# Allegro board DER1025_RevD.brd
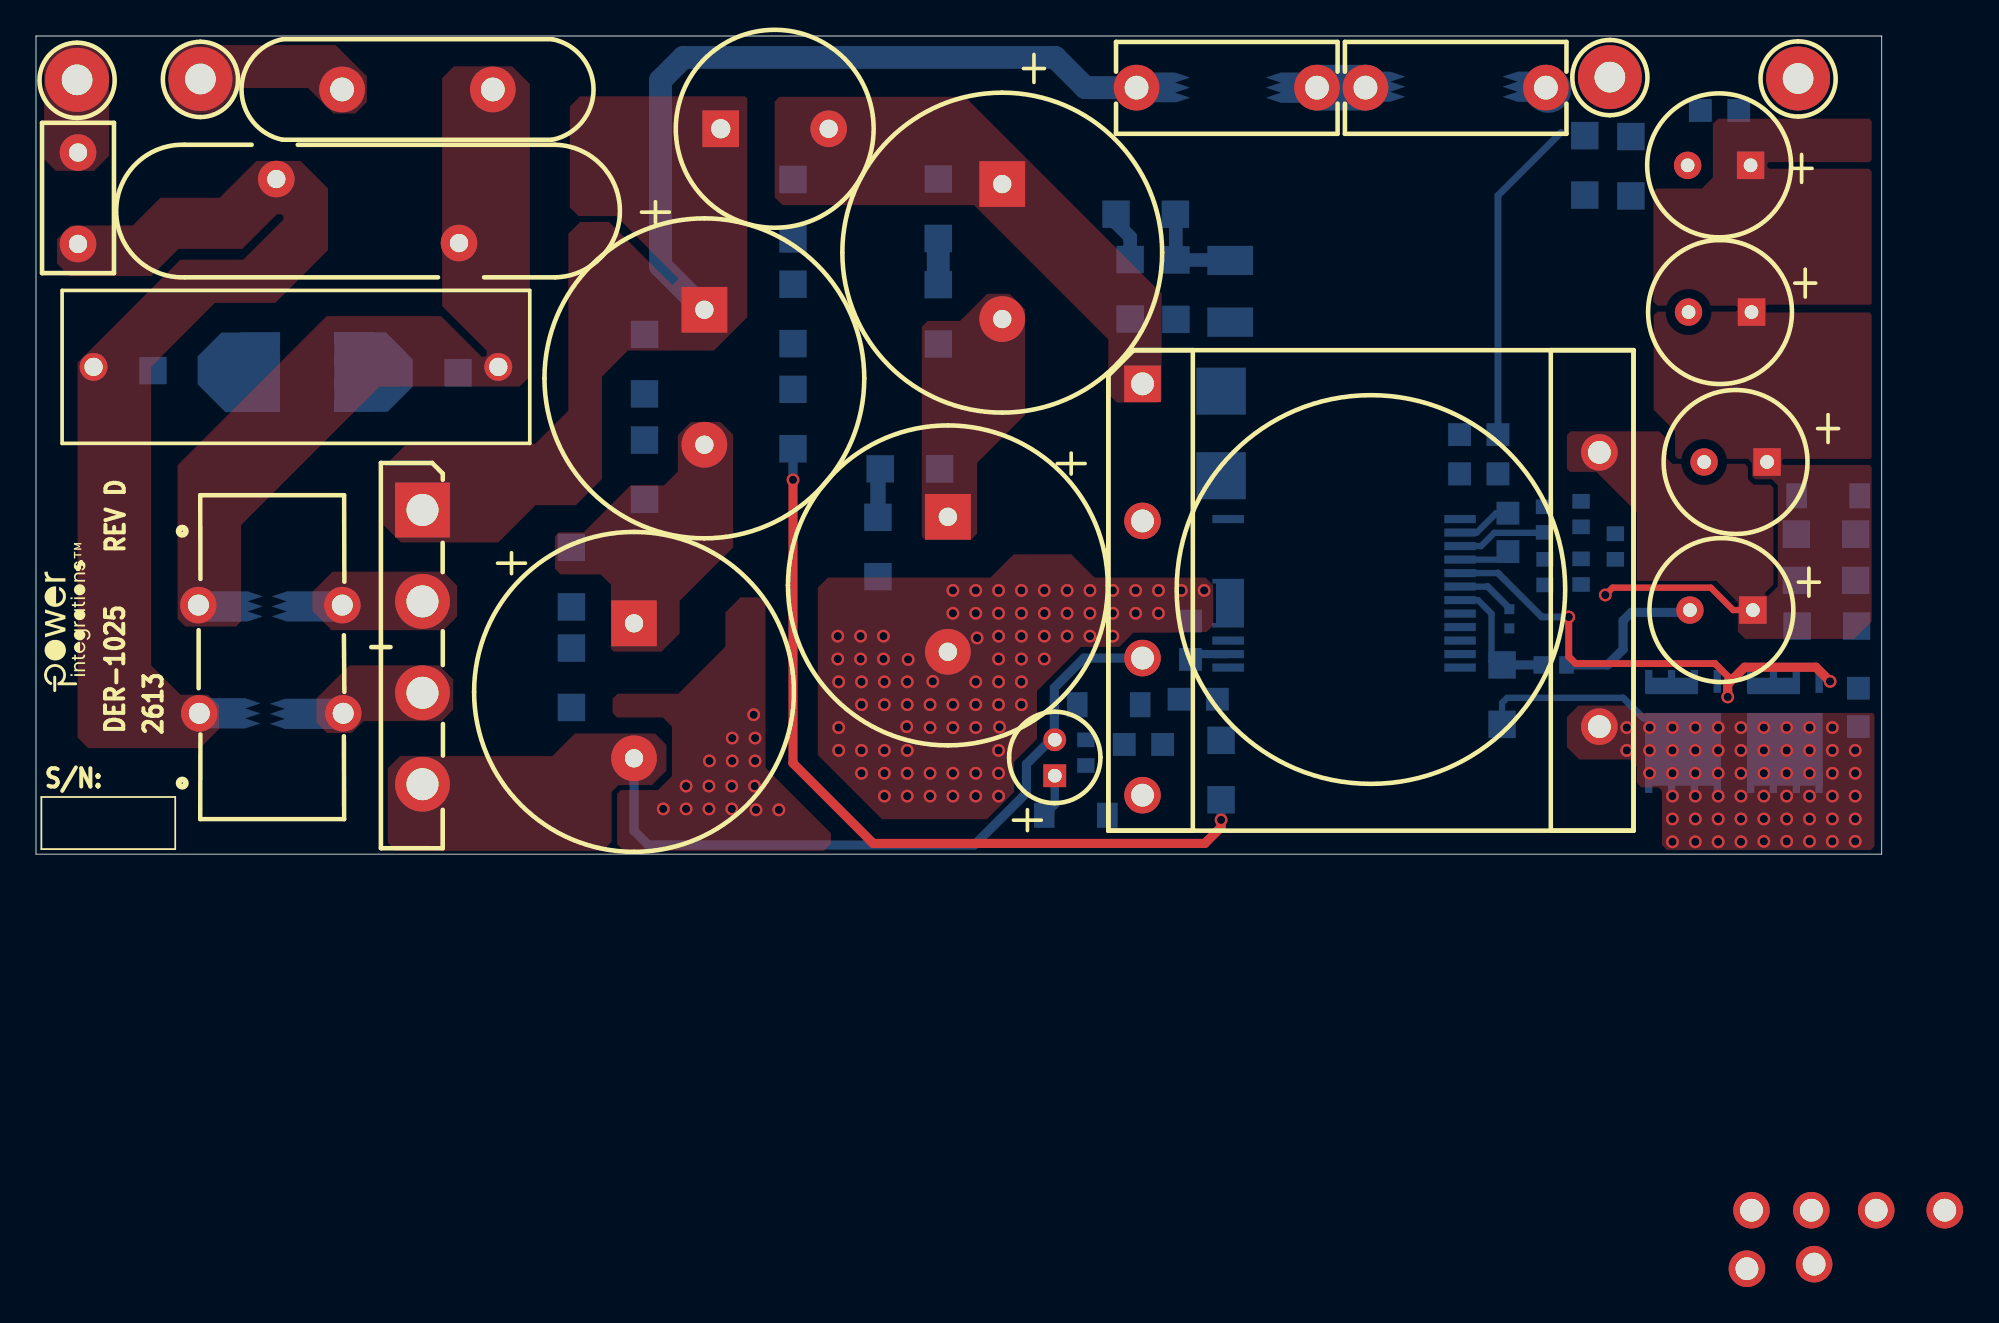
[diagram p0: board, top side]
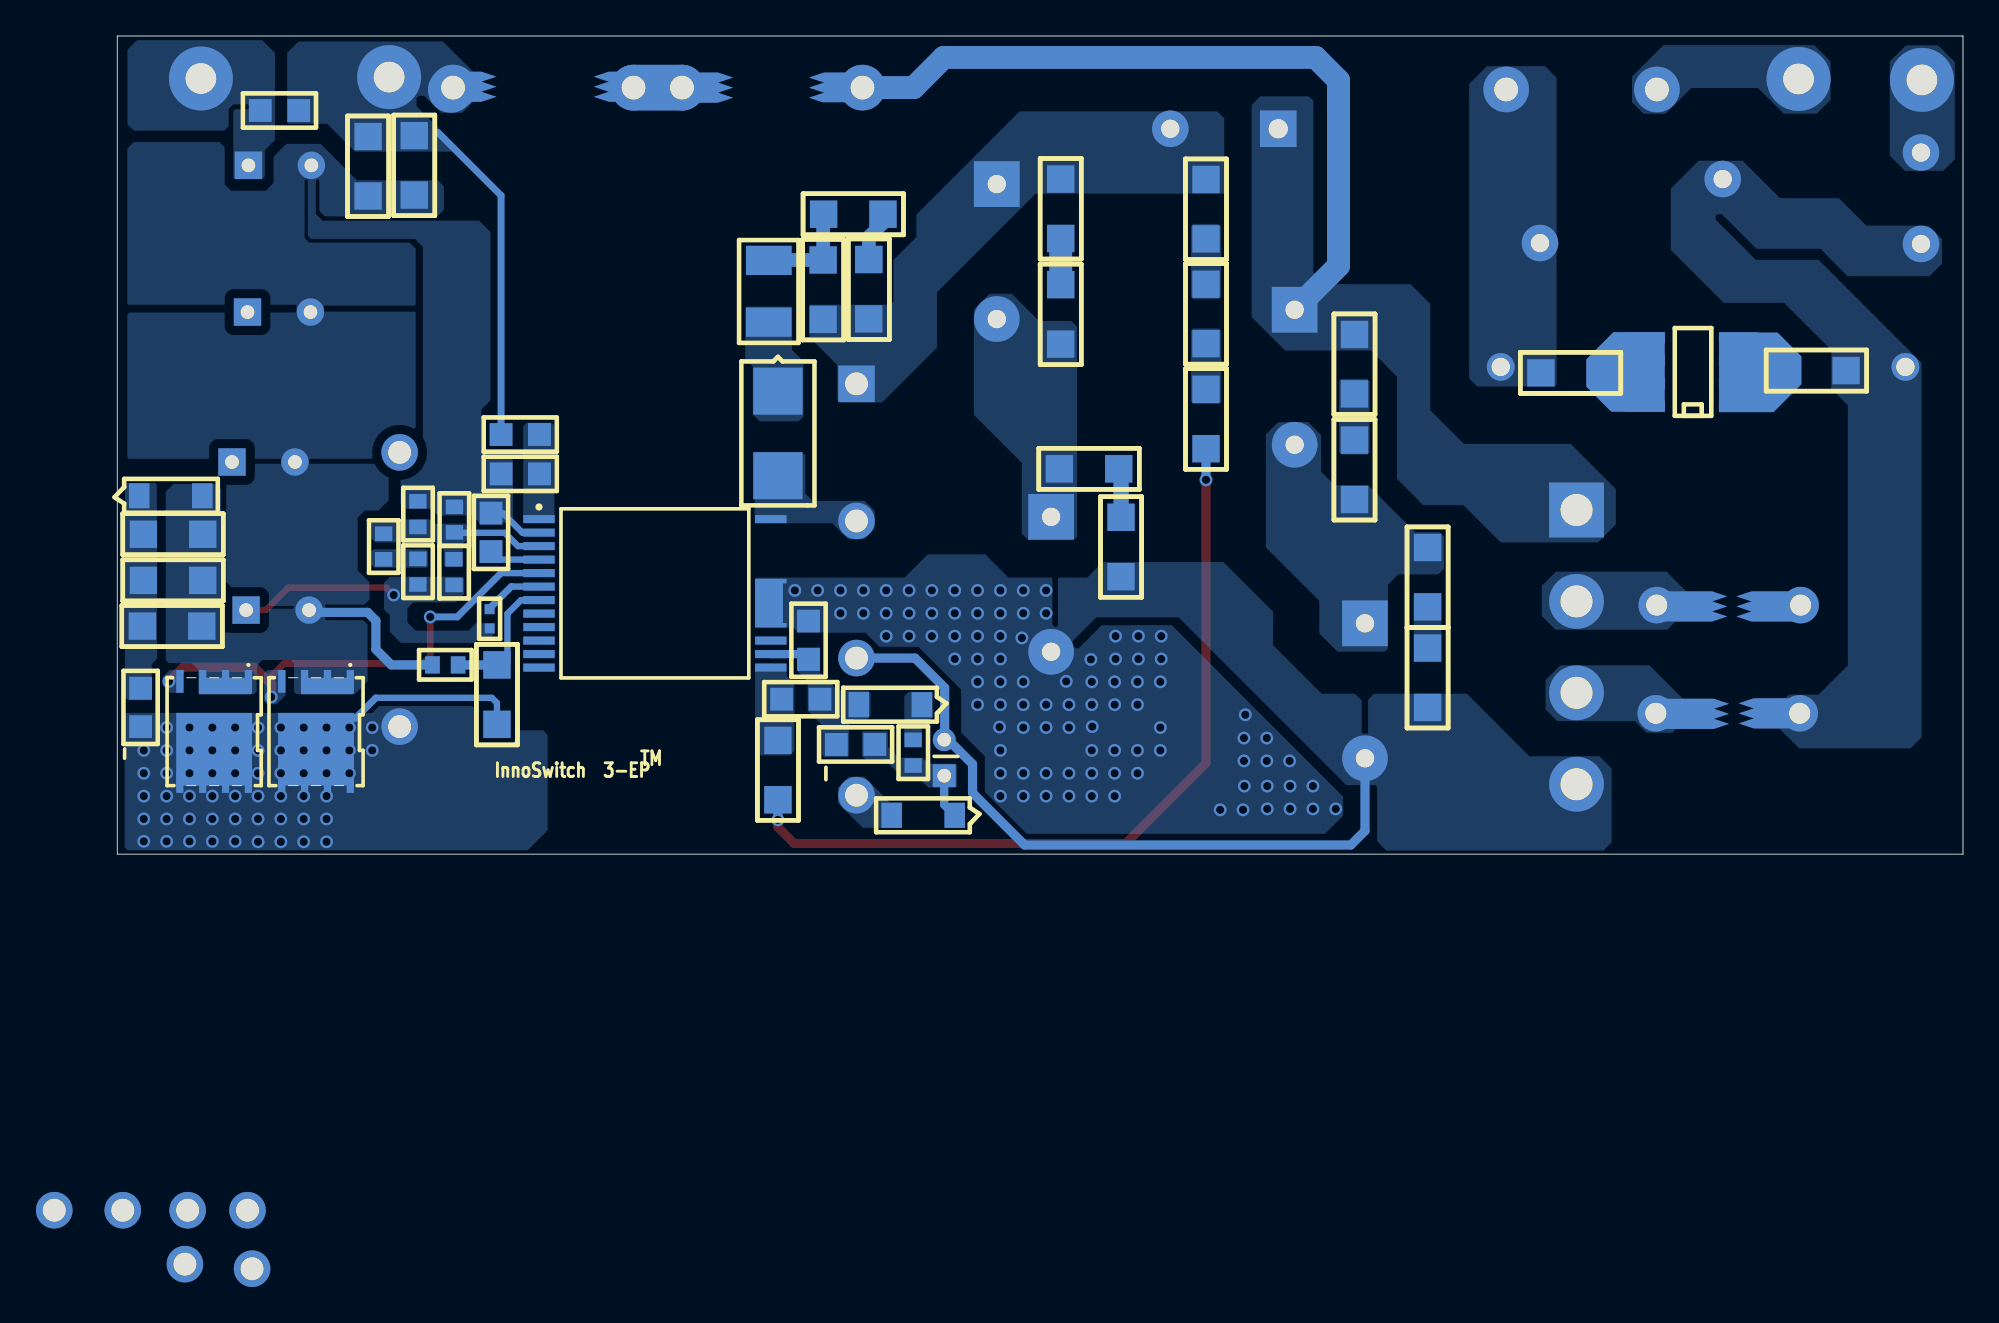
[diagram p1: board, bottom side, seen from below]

Outline 102.62 x 45.47 mm; copper layers: TOP, BOTTOM. Coordinates in mm from the lower left corner of the outline.
Outline path: 0,45.47 0,0 102.62,0 102.62,45.47 0,45.47

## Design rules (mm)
constraint set DEFAULT: min track width 0.203

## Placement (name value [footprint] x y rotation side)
BR1  GBU1010  [PIDAXBRIDGEGBU8]  21.49 19.13 270 top
C1  220 uf  [PIPOLCAPCLYD710LS300040]  37.16 30.25 270 top
C2  220 uf  [PIPOLCAPCLYD710LS300040]  33.25 12.83 270 top
C3  220 uf  [PIPOLCAPCLYD710LS300040]  53.72 37.24 270 top
C4  220 uf  [PIPOLCAPCLYD710LS300040]  50.7 18.75 270 top
C5  1 nF  [PISMC1206]  63.37 29.72 90 bottom
C6  22 uF  [PIPOLCAPCLYD5MMD030]  56.64 5.36 90 top
C7  4.7 uF  [PISMC0805]  64.19 10.82 90 bottom
C8  3.3 nF  [PISMC0805]  101.32 7.09 90 bottom
C9  2.2 uF  [PISMC0805]  81.84 18.95 270 bottom
C10  330 pF  [PISMC0603]  83.67 10.52 0 bottom
C11  4.7 uF  [PISMC0805]  81.28 21.13 180 bottom
C12  330 pF  [PISMC0603]  83.87 19.3 270 bottom
C13  10 nF  [PISMC0603]  87.81 16.38 90 bottom
C14  680 uF  [PIPOLCAPCYLD8MMD030]  95.45 13.56 180 top
C15  680 uF  [PIPOLCAPCYLD8MMD030]  96.24 21.79 180 top
C16  680 uF  [PIPOLCAPCYLD8MMD030]  95.38 30.12 180 top
C17  680 uF  [PIPOLCAPCYLD8MMD030]  95.33 38.28 180 top
C18  2.2 uF  [PISMC0805]  94.67 41.33 180 bottom
CX1  220n  [PINPCAPRAD26X8P5X18D040]  14.45 27.08 0 top
CY1  2.2 nF  [PI_NP475X200LS395D040]  61.19 42.6 0 top
CY2  2.2 nF  [PI_NP475X200LS395D040]  73.91 42.6 0 top
D1  S2T-CT  [PISMDO214AA12]  65.89 25.73 270 bottom
D2  S1MLHRVG  [PI_SM_SOD-123_12]  56.06 2.16 0 bottom
D3  UFM13PL-TP  [PI_SM_SOD-123_12]  101.4 19.91 180 bottom
F1  5 A  [PI_RST_MICROFUSE]  2.34 38.99 270 top
L  WHT  [PITPKEYSTONE125X125]  2.29 43.03 0 top
L1  9 mH  [PI4P18X8MMD046_12_43]  13.13 10.95 90 top
L4  12 uH  [PI_CHOKE_COILCRAFT_RFB1010]  41.07 40.31 0 top
N  BLK  [PITPKEYSTONE125X125]  9.14 43.08 0 top
NOREF  -  []  -317.15 -305.65 0 top
NOREF#2  -  []  0.56 8.46 90 top
NOREF#3  -  []  94.85 -242.24 0 top
NOREF#4  -  []  0 0 90 top
NOREF#5  -  []  0 45.47 0 top
Q1  AON6250  [PISMPQFN5X6B]  89.66 9.6 0 bottom
Q2  AON6250  [PISMPQFN5X6B]  95.33 9.6 0 bottom
R1  56.2 k  [PISMR1206]  6.5 26.87 0 bottom
R2  56.2 k  [PISMR1206]  20.17 26.75 0 bottom
R3  10 M  [PISMR1206]  33.83 28.88 270 bottom
R4  10 M  [PISMR1206]  33.83 23.01 270 bottom
R5  10 M  [PISMR1206]  29.77 17.04 270 bottom
R6  10 M  [PISMR1206]  29.77 11.46 270 bottom
R7  10 M  [PISMR1206]  50.16 37.52 270 bottom
R8  10 M  [PISMR1206]  50.16 31.65 270 bottom
R9  10 M  [PISMR1206]  50.24 21.41 180 bottom
R10  10 M  [PISMR1206]  46.81 18.72 270 bottom
R11  560 k  [PISMR1206]  60.83 29.74 90 bottom
R12  560 k  [PISMR1206]  60.05 35.56 0 bottom
R13  20  [PISMR1210]  66.4 32.99 270 bottom
R14  10  [PISMR0603]  58.37 4.93 90 bottom
R15  7.32 k  [PISMR0805]  60.5 6.1 0 bottom
R16  47.0  [PISMR1206]  81.51 7.21 90 bottom
R17  12  [PISMR1206]  101.17 15.21 180 bottom
R18  12  [PISMR1206]  101.22 12.67 180 bottom
R19  12  [PISMR1206]  101.17 17.78 180 bottom
R20  10  [PISMR0402]  81.92 12.55 90 bottom
R21  102 k  [PISMR0603]  83.9 14.96 90 bottom
R22  11.8 k  [PISMR0603]  85.9 18.19 90 bottom
R23  15 k  [PISMR0603]  85.9 14.99 90 bottom
R24  0.011  [PISMR1206]  86.11 36.63 90 bottom
R25  13 mOhms  [PISMR1206]  88.67 36.58 90 bottom
R32  10  [PISMR0805]  81.28 23.32 180 bottom
R33  210 k  [PISMR0805]  63.55 8.61 0 bottom
R34  2.00 M  [PISMR1206]  42.09 37.49 270 bottom
R35  2.00 M  [PISMR1206]  42.09 31.67 270 bottom
R36  2.00 M  [PISMR1206]  42.09 25.83 270 bottom
R37  1.91 M  [PISMR1206]  65.89 3.02 90 bottom
RT1  5  [PI_RAD770X220LS330D052]  25.4 42.49 180 top
RTN  BLK  [PITPKEYSTONE125X125]  87.5 43.18 0 top
RV1  820V  [PI_DISC1100X290LS400X220D040]  13.36 38.53 0 top
T1  PQ26/20  [PI_BOBBIN_BPQ26_20_12P_2]  74.22 14.71 0 top
U1  CAP200DG  [PI_IC_SMD_SO8_CAPZERO]  12.47 24.89 90 bottom
U2  INN3639C-H606  [PI_IC_INSOP_24D]  79.17 18.62 180 bottom
VO  RED  [PITPKEYSTONE125X125]  97.97 43.1 0 top
VR1  MMSZ5247BT1G  [PI_SM_SOD-123_12]  57.89 8.31 0 bottom

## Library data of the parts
BR1 = DISCRETE BRIDGE_+~~-
C1-C4 = CAP POL: alternate symbols: (pi_cap_cly_d710_ls300_040_1000h,pipolcapd710ls3000401600lhoriz)
C5 C7 C9 C11 C12 CY1 CY2 = CAP NP
C6 = CAP POL: alternate symbols: (pipolcapclyd5x11mmd030H)
C8 C18 = CAP NP: alternate symbols: (Unisem_RMCF0805UL)
C10 C13 = CAP NP: alternate symbols: (Unisem_RMCF0603UL)
C14-C17 = CAP POL: alternate symbols: (pipolcapcyld8x16mmd030H)
CX1 = CAP NP: alternate symbols: (pinpcaprad26x8p5x18d040H)
D1-D3 = DIODE
F1 = FUSE: alternate symbols: (pirstmicrofusehoz)
L = TESTPOINT: alternate symbols: (TP_5010-14)
L1 = TORRID 4P_12_43a
L4 = INDUCTOR
N RTN VO = TESTPOINT
Q1 Q2 = FET_N_SGD_123_4_5678
R1-R14 R16-R19 R24 R25 R32 R34-R37 = R
R15 R33 = R: alternate symbols: (Unisem_RMCF0805UL)
R20 = R: alternate symbols: (Unisem_RMCF0402UL,pismr0402_1)
R21-R23 = R: alternate symbols: (Unisem_RMCF0603UL)
RT1 = THERMISTOR
RV1 = VARISTOR
T1 = BPQ26/20_12P/GENERIC
U1 = CAPZero
U2 = Inno3EP_P15
VR1 = DIODE_ZENER

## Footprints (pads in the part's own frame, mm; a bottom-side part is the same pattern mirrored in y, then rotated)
PI4P18X8MMD046_12_43
  round 2.032 hole 1.168: 1(-3.12,4.051) 2(-3.12,-3.949) 3(2.892,-3.898) 4(2.892,4.102)
PI_BOBBIN_BPQ26_20_12P_2
  rect 2.032x2.032 hole 1.27: 1(-12.7,11.43)
  round 2.032 hole 1.27: 2(20.904,-37.744) 3(-12.7,3.81) 4(-12.7,-3.81) 5(24.638,-37.49) 6(-12.7,-11.43) 7(24.486,-34.493) 8(12.7,-7.62) 9(28.092,-34.493) 10(21.158,-34.493) 11(12.7,7.62) 12(31.902,-34.493)
PI_CHOKE_COILCRAFT_RFB1010
  rect 2.032x2.032 hole 1.067: 1(-3,0)
  round 2.032 hole 1.016: 2(3,0)
PI_DISC1100X290LS400X220D040
  round 2.032 hole 1.016: 1(0,-1.016) 2(10.16,-4.572)
PI_IC_INSOP_24D
  rect 1.75x0.45 smd: 1(0,0) 2(0,-0.75) 3(0,-1.5) 4(0,-2.25) 5(0,-3) 6(0,-3.75) 7(0,-4.5) 8(0,-5.25) 9(0,-6) 10(0,-6.75) 11(0,-7.5) 12(0,-8.25) 13(12.89,-8.25) 14(12.89,-7.5) 15(12.89,-6.75) 24(12.89,0)
  custom 0.438x0.438 smd: 16(12.89,-4.67)
PI_IC_SMD_SO8_CAPZERO
  rect 0.599x2.2 smd: 1(0,0) 2(1.27,0) 3(2.54,0) 4(3.81,0) 5(3.81,5.199) 6(2.54,5.199) 7(1.27,5.199) 8(0,5.199)
PI_NP475X200LS395D040
  round 2.54 hole 1.321: 1(0,0) 2(10.033,0)
PI_RAD770X220LS330D052
  round 2.54 hole 1.321: 1(0,0) 2(8.382,0)
PI_RST_MICROFUSE
  round 2.032 hole 1.016: 1(0,0) 2(5.08,0)
PI_SM_SOD-123_12
  rect 1.143x1.397 smd: 1(0,0) 2(3.505,0)
PIDAXBRIDGEGBU8
  rect 3.048x3.048 hole 1.778: 1(0,0)
  round 3.048 hole 1.778: 2(5.08,0) 3(10.16,0) 4(15.24,0)
PINPCAPRAD26X8P5X18D040
  round 1.549 hole 1.016: 1(-11.25,0) 2(11.25,0)
PIPOLCAPCLYD5MMD030
  rect 1.27x1.27 hole 0.762: 1(-1,0)
  round 1.27 hole 0.762: 2(1,0)
PIPOLCAPCLYD710LS300040
  rect 2.54x2.54 hole 1.016: 1(0,0)
  round 2.54 hole 1.016: 2(7.5,0)
PIPOLCAPCYLD8MMD030
  rect 1.524x1.524 hole 0.762: 1(0,0)
  round 1.524 hole 0.762: 2(3.5,0)
PISMC0603
  rect 0.813x0.965 smd: 1(0,0) 2(1.422,0)
PISMC0805
  rect 1.27x1.27 smd: 1(0,0) 2(2.134,0)
PISMC1206
  rect 1.524x1.524 smd: 1(0,0) 2(3.302,0)
PISMDO214AA12
  rect 2.616x2.743 smd: 1(0,0) 2(4.699,0)
PISMPQFN5X6B
  rect 0.406x1.27 smd: 1(0,0) 2(1.27,0) 3(2.54,0) 4(3.81,0)
  rect 0.406x1.219 smd: 5(3.81,5.588) 6(2.54,5.588) 7(1.27,5.588) 8(0,5.588)
PISMR0402
  rect 0.559x0.559 smd: 1(0,0) 2(1.067,0)
PISMR0603
  rect 0.813x0.965 smd: 1(0,0) 2(1.422,0)
PISMR0805
  rect 1.27x1.27 smd: 1(0,0) 2(2.134,0)
PISMR1206
  rect 1.524x1.524 smd: 1(0,0) 2(3.302,0)
PISMR1210
  rect 1.626x2.54 smd: 1(0,0) 2(3.429,0)
PITPKEYSTONE125X125
  round 3.556 hole 1.702: 1(0,0)

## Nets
GND: BR1.4 C2.2 C4.2 C6.2 C7.2 R6.2 R10.2 T1.4 U2.16
GND SIGNAL: C18.2 CY2.2 R24.2 R25.2 R32.1 RTN.1
NC8: U2.8
NC9: U2.9
NC10: U2.10
NC11: U2.11
NC12: U2.12
RTN: C11.2 R32.2 U2.1
VO: C14.1 C15.1 C16.1 C17.1 C18.1 R20.1 R21.1 R23.1 T1.11 VO.1
N37461: C8.2 D3.1 R17.1 R18.1 R19.1
N37469: C9.1 C10.2 C11.1 C12.1 C14.2 C15.2 C16.2 C17.2 D3.2 Q1.1 Q1.2 Q1.3(S3) Q2.1 Q2.2 Q2.3(S3) R17.2 R18.2 R19.2 R22.2 R24.1 R25.1 U2.2
N38055: C6.1 D2.1 R14.1 R15.1
N38189: C7.1 R15.2 R33.1 U2.14 VR1.2
N100542: D1.1 R13.2
N100730: C5.2 R12.2 R13.1
N100745: C3.1 C5.1 L4.2 R7.1 R11.1 R34.1 T1.1
N100844: R11.2 R12.1
N104424: C8.1 Q1.5 Q1.6 Q1.7 Q1.8 Q2.5 Q2.6 Q2.7 Q2.8 R16.1 T1.8
N108780: C12.2 C13.2 R21.2 R22.1 U2.3
N109833: C13.1 R23.2
N12293127: C10.1 R16.2 U2.7
N12305547: Q1.4 Q2.4 U2.5
N12342924: D1.2 T1.3 U2.24
N12352620: C3.2 C4.1 R8.2 R9.1
N12353333: BR1.1 C1.1 CY1.1 L4.1 R3.1
N12359836: R7.2 R8.1
N12360252: R9.2 R10.1
N12374653: R3.2 R4.1
N12374691: C1.2 C2.1 R4.2 R5.1
N12374751: R5.2 R6.1
N12405316: BR1.3(AC2) L1.2
N12405324: BR1.2 L1.3
N12405376: CX1.1 F1.2 L1.1 R1.1 RV1.1
N12405380: CX1.2 L1.4 R2.2 RT1.1 RV1.2
N12407233: F1.1 L.1
N12407237: N.1 RT1.2
N12426226: R20.2 U2.6
N12433777: D2.2 T1.6
N12606053: R14.2 VR1.1
N13222962: R1.2 U1.2
N13223037: R2.1 U1.7
N13228168: R33.2 R37.2 U2.13(VPIN)
N13228288: R34.2 R35.1
N13228295: R35.2 R36.1
N13228312: R36.2 R37.1
N13231702: C9.2 U2.4
N13238248: CY1.2 CY2.1

Pads without a net: T1 2 5 7 9 10 12; U1 1 3 4 5 6 8; U2 15

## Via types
v1: diameter 0.711, hole 0.457, TOP to BOTTOM, 159 vias

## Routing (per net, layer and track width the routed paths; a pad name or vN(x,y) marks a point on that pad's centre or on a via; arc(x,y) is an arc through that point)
GND: length 39.6
  BOTTOM w0.457: 56.62,6.34 56.63,6.36 C6.2
  BOTTOM w0.508: 56.62,6.36 56.64,6.33 ; 56.62,6.36 56.62,6.34 56.41,6.34 55.07,5 55.07,3.4 52.17,0.51 34.04,0.51 33.25,1.3 C2.2 ; 56.62,6.36 56.62,9.25 58.27,10.9 T1.4
  vias: v1(34.87,2.51) v1(36.14,3.78) v1(36.14,2.51) v1(37.44,5.18) v1(37.41,3.78) v1(37.41,2.51) v1(38.71,6.45) v1(38.71,5.18) v1(38.68,3.78) v1(38.68,2.51) v1(39.9,7.75) v1(39.98,6.45) v1(39.98,5.18) v1(39.95,3.78) v1(40.03,2.46) v1(41.3,2.46) v1(44.58,12.12) v1(44.58,10.85) v1(44.63,9.58) v1(44.63,7.04) v1(44.63,5.77) v1(45.85,12.12) v1(45.85,10.85) v1(45.9,9.58) v1(45.9,8.31) v1(45.9,5.77) v1(45.9,4.5) v1(47.12,12.12) v1(47.12,10.85) v1(47.17,9.58) v1(47.17,8.31) v1(47.17,5.77) v1(47.17,4.5) v1(47.17,3.23) v1(48.44,9.58) v1(48.44,8.31) v1(48.41,7.09) v1(48.44,5.77) v1(48.44,4.5) v1(48.44,3.23) v1(48.49,10.82) v1(49.71,8.31) v1(49.71,7.04) v1(49.71,4.5) v1(49.71,3.23) v1(49.86,9.6) v1(50.98,14.66) v1(50.98,13.39) v1(50.98,8.31) v1(50.98,7.04) v1(50.98,4.5) v1(50.98,3.23) v1(52.25,14.66) v1(52.25,13.39) v1(52.25,9.58) v1(52.25,8.31) v1(52.25,7.04) v1(52.25,4.5) v1(52.25,3.23) v1(52.32,12.01) v1(53.52,14.66) v1(53.52,13.39) v1(53.52,12.12) v1(53.52,10.85) v1(53.52,9.58) v1(53.52,8.31) v1(53.52,5.77) v1(53.52,4.5) v1(53.52,3.23) v1(53.57,7.06) v1(54.79,14.66) v1(54.79,13.39) v1(54.79,12.12) v1(54.79,10.85) v1(54.79,9.58) v1(54.79,8.31) v1(56.06,14.66) v1(56.06,13.39) v1(56.06,12.12) v1(56.06,10.85) v1(57.33,14.66) v1(57.33,13.39) v1(57.33,12.12) v1(58.6,14.66) v1(58.6,13.39) v1(58.6,12.12) v1(59.87,14.66) v1(59.87,13.39) v1(59.87,12.12) v1(61.14,14.66) v1(61.14,13.39) v1(62.41,14.66) v1(62.41,13.39) v1(63.68,14.66) v1(64.95,14.66)
GND SIGNAL: length 18.4
  BOTTOM w0.381: R32.1 81.28,36.6 84.79,40.11
  BOTTOM w2.54: CY2.2 84.07,42.47
VO: length 9
  TOP w0.35: v1(87.25,14.4) 87.66,14.81 93.12,14.81 94.36,13.56 C14.1
  BOTTOM w0.254: 81.97,12.55 81.92,12.6
N37469: length 12.2
  BOTTOM w0.35: 81.23,18.95 81.18,18.95 80.1,17.87 U2.2
  BOTTOM w0.381: 81.86,18.95 C9.1 81.23,18.95
  BOTTOM w0.508: C10.2 87.38,10.52 88.24,11.38 88.24,12.98 88.7,13.44 91.83,13.44 C14.2
N38055: length 2.4
  BOTTOM w0.457: D2.1 56.64,2.74 C6.1
N38189: length 2.2
  BOTTOM w0.457: U2.14 64.48,11.12 C7.1
N100730: length 5.6
  BOTTOM w0.762: R12.2 63.37,35.53 C5.2 66.37,33.02 R13.1
N100844: length 2.8
  BOTTOM w0.762: R12.1 60.07,35.53 60.07,35.05 60.83,34.29 R11.2
N104424: length 9.7
  BOTTOM w0.35: 88.24,8.69 81.79,8.69 81.51,8.4 R16.1
  BOTTOM w0.381: 89.38,7.54 88.24,8.69
  vias: v1(88.44,7.04) v1(88.44,5.77) v1(89.71,7.04) v1(89.71,5.77) v1(89.71,4.5) v1(90.98,7.04) v1(90.98,5.77) v1(90.98,4.5) v1(90.98,3.23) v1(90.98,1.96) v1(90.98,0.69) v1(92.25,7.04) v1(92.25,5.77) v1(92.25,4.5) v1(92.25,3.23) v1(92.25,1.96) v1(92.25,0.69) v1(93.52,7.04) v1(93.52,5.77) v1(93.52,4.5) v1(93.52,3.23) v1(93.52,1.96) v1(93.52,0.69) v1(94.79,7.04) v1(94.79,5.77) v1(94.79,4.5) v1(94.79,3.23) v1(94.79,1.96) v1(94.79,0.69) v1(96.06,7.04) v1(96.06,5.77) v1(96.06,4.5) v1(96.06,3.23) v1(96.06,1.96) v1(96.06,0.71) v1(97.33,7.04) v1(97.33,5.77) v1(97.33,4.5) v1(97.33,3.23) v1(97.33,1.96) v1(97.33,0.71) v1(98.6,7.04) v1(98.6,5.77) v1(98.6,4.5) v1(98.6,3.23) v1(98.6,1.96) v1(98.6,0.71) v1(99.87,7.04) v1(99.87,5.77) v1(99.87,4.5) v1(99.87,3.23) v1(99.87,1.96) v1(99.87,0.71) v1(101.14,5.77) v1(101.14,4.5) v1(101.14,3.23) v1(101.14,1.96) v1(101.14,0.71)
N108780: length 5
  BOTTOM w0.35: C12.2 83.85,17.86 81.08,17.86 80.34,17.12 U2.3
N12293127: length 7.5
  BOTTOM w0.35: U2.7 80.17,14.12 80.92,13.36 80.92,10.69 81.1,10.52 R16.2
  BOTTOM w0.508: R16.2 C10.1
N12305547: length 26.1
  TOP w0.381: v1(85.22,13.18) 85.22,10.97 85.6,10.59 93.34,10.59 94.06,9.88 94.06,9.45
  TOP w0.508: v1(99.75,9.6) 98.96,10.39 95,10.39 94.06,9.45 v1(94.06,8.74)
  BOTTOM w0.35: 81.27,15.63 81.27,15.62 U2.5
  BOTTOM w0.381: v1(85.22,13.18) 83.72,13.18 81.27,15.63
N12342924: length 0.4
  BOTTOM w0.381: 66.29,21.01 65.91,21.01 D1.2 ; 61.57,18.62 61.58,18.63
N12353333: length 41.7
  BOTTOM w1.27: C1.1 34.72,32.69 34.72,43 35.99,44.27 56.67,44.27 58.34,42.6 CY1.1 61.01,42.42
N12359836: length 2.6
  BOTTOM w1.27: R7.2 R8.1
N12360252: length 2.7
  BOTTOM w0.85: R10.1 46.81,21.29 R9.2
N12426226: length 3.3
  BOTTOM w0.35: 80.7,14.88 80.7,14.87 U2.6 ; 81.92,13.67 R20.2
  BOTTOM w0.381: 80.7,14.88 81.92,13.67
N13228312: length 45
  TOP w0.508: v1(42.09,20.8) 42.09,5.05 46.55,0.6 64.99,0.6 65.89,1.5 v1(65.89,1.91)
  BOTTOM w0.508: R36.2 v1(42.09,20.8) ; R37.1 v1(65.89,1.91)
N13231702: length 2.9
  BOTTOM w0.35: U2.4 81.39,16.37 C9.2
  BOTTOM w0.381: 81.86,16.81 C9.2
N13238248: length 2.7
  BOTTOM w2.54: CY1.2 CY2.1

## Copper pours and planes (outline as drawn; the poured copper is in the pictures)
GND on TOP: 29.96,6.71 34.42,6.71 35.05,6.07 35.05,4.65 34.24,3.84 32.38,3.84 32,3.45 32,0.69 31.5,0.18 20.02,0.18 19.56,0.64 19.56,4.77 20.24,5.45 28.71,5.45
GND on TOP: 53.06,15.37 54.35,16.66 57.56,16.66 58.86,15.37 65.02,15.37 65.46,14.94 65.46,12.73 65.07,12.34 63.68,12.34 63.68,12.32 63.3,12.32 63.28,12.31 61.02,12.31 60.24,11.52 58.1,11.52 55.65,9.07 55.65,6.4 54.38,5.13 54.38,3.45 52.87,1.94 47.03,1.94 43.46,5.51 43.46,14.8 44.03,15.37
GND on TOP: 40.56,4.8 44.2,1.17 44.2,0.58 43.79,0.18 32.69,0.18 32.31,0.56 32.31,3.35 32.51,3.56 34.57,3.56 35.36,4.34 35.36,7.09 34.85,7.59 32.31,7.59 32.05,7.85 32.05,8.64 32.33,8.92 35.71,8.92 38.33,11.53 38.33,13.44 39.17,14.27 40.18,14.27 40.56,13.89
GND on BOTTOM: 54.36,16.66 57.56,16.66 58.85,15.37 67.13,15.37 67.13,12.65 67.08,12.6 65.05,12.6 64.77,12.32 63.3,12.32 63.28,12.31 61.02,12.31 60.24,11.52 58.08,11.52 55.7,9.14 55.7,6.76 54.38,5.44 54.38,3.45 52.06,1.13 35.47,1.13 34.47,2.13 34.47,3.2 43.99,12.73 46.25,12.73 46.27,12.71 47.89,12.71 49.16,11.44 49.34,11.44 49.51,11.61 49.51,11.84 48.18,13.16 43.56,13.16 43.56,13.11 34.29,3.84 32.68,3.84 32.57,3.72 32.57,0.72 32.05,0.2 19.99,0.2 19.53,0.66 19.53,4.76 20.21,5.44 24.11,5.44 27.58,8.92 32.74,8.92 33.08,8.58 33.08,6.73 33.1,6.71 33.4,6.71 33.43,6.73 33.43,8.53 33.81,8.92 35.66,8.92 38.35,11.61 38.35,13.47 41.12,16.23 47.83,16.23 48.69,15.37 50.27,15.37 50.32,15.32 50.32,12.7 50.39,12.62 50.5,12.62 50.62,12.75 50.62,15.29 50.7,15.37 53.06,15.37
GND SIGNAL on BOTTOM (solid shape): 84.07,41.81 82.37,41.81 81.53,42.09 82.37,42.37 81.53,42.65 82.37,42.93 81.53,43.21 82.37,43.48 84.07,43.48
GND SIGNAL on BOTTOM: 84.51,45.16 82.73,43.39 82.73,41.9 83.44,41.2 84.61,41.2 85.05,41.64 85.06,41.64 85.55,42.14 85.85,42.14 85.98,42.02 85.98,41.57 83.87,39.46 83.87,39.09 83.92,39.04 89.4,39.04 90.95,40.59 93.1,40.59 93.17,40.67 93.17,44.53 92.54,45.16
RTN on BOTTOM: 80.05,23.79 79.86,23.98 78.46,23.98 78.32,23.83 78.32,18.62 78.43,18.51 79.89,18.51 80.05,18.67
VO on TOP: outline of 83 points within 85.12,11.96 102.06,40.87
VO on BOTTOM: 87.45,15.42 87.78,15.09 87.78,13.59 87.46,13.27 87.46,12.35 86.85,11.74 82.77,11.74 82.44,12.06 81.83,12.06 81.63,12.26 81.63,12.83 82.27,12.83 82.27,12.83 82.69,12.83 83.09,12.42 86.03,12.42 86.49,12.88 86.49,13.67 86.16,14 83.79,14 83.33,14.46 83.33,15.3 83.45,15.42
VO on BOTTOM: 94.56,45.24 101.52,45.24 102.05,44.7 102.05,40.56 101.7,40.21 96.65,40.21 96.42,40.44 96.42,41.4 96.16,41.66 95.35,41.66 95.3,41.62 95.3,41.43 95.33,41.4 96.06,41.4 96.16,41.3 96.16,37.59 96.09,37.51 94.57,37.51 94.41,37.67 94.41,39.12 93.85,39.67 93.85,44.53
N37461 on BOTTOM: 102.18,8.71 102.03,8.56 100.7,8.56 100.7,10.56 100.41,10.86 100.41,18.08 100.42,18.1 100.42,20.54 100.51,20.62 102.11,20.62 102.18,20.55
N37469 on BOTTOM (solid shape): 92.41,8.89 89.48,8.89 89.48,9.8 92.41,9.8
N37469 on BOTTOM (solid shape): 98.07,8.89 95.15,8.89 95.15,9.8 98.07,9.8
N37469 on BOTTOM: outline of 146 points within 80.62,8.89 102.06,39.58
N38055 on BOTTOM: 57.51,5.03 57.84,5.36 59.16,5.36 59.77,5.96 59.77,6.76 59.84,6.83 61.16,6.83 61.21,6.78 61.21,5.46 61.01,5.26 59.97,5.26 58.95,4.24 58.06,4.24 57.53,3.71 56.01,3.71 55.93,3.78 55.93,4.93 56.03,5.03
N38189 on BOTTOM: 63.55,11.51 64.77,11.51 64.82,11.46 64.82,10.19 64.24,9.6 64.24,7.98 63.42,7.16 63.42,5.51 63.3,5.38 62.03,5.38 61.93,5.49 61.93,7.24 61.67,7.49 60.93,7.49 60.73,7.7 60.73,8.94 60.88,9.09 62.56,9.09 63.55,10.08
N100542 on BOTTOM: 65.17,30.43 67.64,30.43 67.7,30.37 67.7,27.52 67.28,27.1 67.28,24.43 66.9,24.05 64.72,24.05 64.47,24.31 64.47,27.38 65.11,28.02 65.11,30.36
N100745 on TOP: 62.59,25.27 62.41,25.1 60.1,25.1 59.61,25.58 59.61,28.6 52.15,36.07 41.5,36.07 41.07,36.5 41.07,41.83 41.33,42.09 51.65,42.09 62.59,31.15
N100745 on BOTTOM: 58.19,34.29 59.46,33.02 59.46,30.71 59.64,30.53 64.09,30.53 64.13,30.49 64.13,28.72 62.59,27.18 62.59,25.27 62.41,25.1 60.1,25.1 57.05,28.14 57.05,31.22 51.56,36.7 41.07,36.7 41.07,40.89 41.45,41.28 52.45,41.28 58.19,35.53
N104424 on BOTTOM (solid shape): 93.68,3.81 89.46,3.81 89.46,7.85 93.68,7.85
N104424 on BOTTOM (solid shape): 99.34,3.81 95.12,3.81 95.12,7.85 99.34,7.85
N104424 on TOP: 88.44,8.26 88.85,7.85 102.11,7.85 102.21,7.75 102.21,0.43 102.01,0.23 90.68,0.23 90.4,0.51 90.4,3.51 90.2,3.71 89.26,3.71 89,3.96 89,4.88 88.62,5.26 85.8,5.26 85.12,5.94 85.12,7.62 85.75,8.26
N104424 on BOTTOM: 102.11,7.85 102.21,7.75 102.21,0.38 102.04,0.22 79.79,0.22 78.69,1.32 78.69,6.63 78.94,6.88 80.26,6.88 80.49,6.65 80.49,6.35 80.64,6.2 82.5,6.2 82.6,6.3 82.6,7.95 82.88,8.23 88.06,8.23 88.44,7.85
N108780 on BOTTOM: 85.01,18.36 85.25,18.6 88.25,18.6 88.49,18.36 88.49,17.55 88.27,17.32 84.89,17.32 84.45,16.89 84.45,16.04 84.39,15.98 83.41,15.98 83.41,17.25 82.91,17.75 82.91,17.98 83.29,18.36
N109833 on BOTTOM: 88.37,16.94 85.45,16.94 85.34,16.84 85.34,16.02 85.44,15.92 88.31,15.92 88.47,16.08 88.47,16.84
N12305547 on BOTTOM: 94.46,8.51 94.28,8.33 93.75,8.33 93.27,8.81 93.27,10.24 94.26,10.24 94.46,10.03
N12305547 on BOTTOM: 98.93,10.24 99.69,10.24 100.1,9.83 100.1,9.5 100.1,9.5 100.1,9.39 99.68,8.97 98.93,8.97 98.93,10.23
N12342924 on BOTTOM: 67.18,18.39 62.87,18.39 61.98,17.5 61.09,17.5 60.5,18.08 60.5,19.08 61.06,19.63 63.96,19.63 64.36,20.04 64.36,22.15 64.52,22.3 67.18,22.3
N12352620 on TOP: 52.88,31.14 51.59,29.84 51.58,29.84 51.37,29.63 49.57,29.63 49.25,29.31 49.25,17.64 49.42,17.48 51.99,17.48 52.32,17.81 52.32,21.74 55,24.42 55,30.27 54.13,31.14
N12352620 on BOTTOM: 52.88,31.14 51.37,29.63 49.57,29.63 49.25,29.31 49.25,17.65 49.42,17.48 51.99,17.48 52.32,17.81 52.32,21.74 54.99,24.41 54.99,30.27 54.12,31.14
N12353333 on BOTTOM (solid shape): 64.16,43.15 63.32,42.88 64.16,42.6 63.32,42.32 64.16,42.04 63.4,41.78 60.31,41.78 60.31,43.43 63.32,43.43
N12353333 on TOP: 35.38,31.62 35.74,31.98 32.26,35.46 30.17,35.46 29.68,35.95 29.68,41.54 30.25,42.11 39.42,42.11 39.55,41.99 39.55,29.84 37.69,27.99 32.92,27.99 31.47,26.54 31.47,20.85 30.01,19.39 27.78,19.39 25.7,17.32 20.29,17.32 19.3,18.31 19.3,21.49 20.62,22.8 27.75,22.8 29.6,24.65 29.6,34.48 30.25,35.13 31.88,35.13
N12353333 on BOTTOM: 30.71,31.67 35.33,31.67 35.38,31.62 36.12,32.36 36.12,41.86 36.37,42.11 39.07,42.11 39.55,41.63 39.55,29.84 37.69,27.99 32.92,27.99 31.47,26.54 31.47,20.85 30.01,19.39 27.77,19.39 25.7,17.32 20.29,17.32 19.3,18.31 19.3,20.29 21.81,22.8 27.75,22.8 29.62,24.66 29.62,30.58
N12374653 on BOTTOM: 33.13,26.42 34.57,26.42 34.68,26.3 34.68,22.34 34.54,22.2 33.11,22.2 32.99,22.31 32.99,26.28
N12374691 on TOP: 38.07,24 36.4,24 35.69,23.29 35.69,21.26 34.93,20.5 33.06,20.5 30.45,17.89 29.06,17.89 28.85,17.68 28.85,15.86 29.16,15.54 31.39,15.54 31.97,14.97 31.97,11.41 32.12,11.25 34.77,11.25 35.79,12.27 35.79,14.07 38.76,17.04 38.76,23.32
N12374691 on BOTTOM: 38.07,24 36.4,24 35.69,23.29 35.69,21.26 34.92,20.5 33.06,20.5 30.45,17.89 29.08,17.89 28.85,17.66 28.85,15.86 29.17,15.54 31.39,15.54 31.97,14.96 31.97,11.4 32.13,11.25 34.77,11.25 35.79,12.27 35.79,14.07 38.76,17.04 38.76,23.32
N12374751 on BOTTOM: 30.51,14.5 30.53,14.48 30.53,10.69 30.51,10.67 29.01,10.67 29.01,14.5 29.01,14.5
N12405316 on BOTTOM (solid shape): 16.89,6.96 13.84,6.96 13,7.24 13.84,7.52 13,7.8 13.84,8.08 13,8.36 13.84,8.64 16.89,8.64
N12405316 on TOP: 22.42,10.49 17.42,10.49 15.6,8.66 15.6,7.32 16.18,6.73 17.55,6.73 18.21,7.39 22.56,7.39 23.2,8.03 23.2,9.71
N12405316 on BOTTOM: 22.39,10.49 17.42,10.49 15.6,8.66 15.6,7.32 16.15,6.76 17.6,6.76 18.24,7.39 22.56,7.39 23.21,8.04 23.21,9.67
N12405324 on BOTTOM (solid shape): 16.97,12.93 13.94,12.93 13.11,13.21 13.94,13.49 13.11,13.77 13.94,14.05 13.11,14.33 13.94,14.61 16.97,14.61
N12405324 on TOP: 22.64,15.7 23.42,14.92 23.42,13.21 22.66,12.45 16.43,12.45 15.37,13.51 15.37,14.58 16.49,15.7
N12405324 on BOTTOM: 23.42,14.91 23.42,13.23 22.66,12.47 16.43,12.47 15.37,13.54 15.37,14.59 16.48,15.7 22.63,15.7
N12405376 on BOTTOM (solid shape): 12.47,8.38 11.63,8.1 12.47,7.82 11.63,7.54 12.47,7.26 11.63,6.99 8.81,6.99 8.81,8.66 11.63,8.66
N12405376 on TOP: 12.26,38.52 14.71,38.52 16.24,36.99 16.24,33.57 13.31,30.64 9.95,30.64 6.4,27.09 6.4,10.49 8.03,8.86 9.58,8.86 10.19,8.26 10.19,6.96 9.12,5.89 2.9,5.89 2.31,6.48 2.31,27.32 8.03,33.03 11.52,33.03 13.76,35.27 13.76,35.45 13.65,35.56 13.39,35.56 11.47,33.63 7.92,33.63 6.41,32.12 1.88,32.12 1.17,32.83 1.17,34.17 1.93,34.93 5.37,34.93 6.92,36.47 10.21,36.47
N12405376 on BOTTOM: 16.25,36.98 16.25,33.58 13.31,30.64 9.94,30.64 7.32,28.02 7.32,25.86 6.4,24.94 6.4,10.49 8.03,8.86 9.68,8.86 10.41,8.13 10.41,7.19 9.11,5.88 2.91,5.88 2.31,6.48 2.31,27.31 8.03,33.03 11.52,33.03 12.13,33.64 12.13,33.64 13.75,35.27 13.75,35.47 13.66,35.56 13.41,35.56 11.78,33.94 11.78,33.93 11.49,33.64 7.92,33.64 7.41,33.12 7.41,33.11 6.42,32.12 1.86,32.12 1.17,32.81 1.17,34.17 1.92,34.93 5.37,34.93 6.9,36.46 10.18,36.46 12.26,38.54 14.7,38.54
N12405380 on BOTTOM (solid shape): 12.6,14.33 11.76,14.05 12.6,13.77 11.76,13.49 12.6,13.21 11.76,12.93 8.66,12.93 8.66,14.61 11.76,14.61
N12405380 on TOP: 27.46,42.8 27.46,26.54 26.9,25.99 19.1,25.99 11.4,18.29 11.4,12.93 11.12,12.65 8.31,12.65 7.87,13.08 7.87,21.62 16.15,29.9 22.53,29.9 24.78,27.65 24.97,27.65 25.06,27.74 25.06,27.98 22.58,30.45 22.58,43.13 23.23,43.78 26.48,43.78
N12405380 on BOTTOM: 27.46,42.8 27.46,26.43 27.01,25.99 22.71,25.99 22.6,26.1 22.6,43.15 23.24,43.79 26.47,43.79
N12407233 on TOP: 4.07,44.03 4.07,38.81 3.23,37.98 1.1,37.98 0.46,38.61 0.46,44.02 1.39,44.95 3.15,44.95
N12407233 on BOTTOM: 4.07,38.82 3.23,37.98 1.1,37.98 0.46,38.62 0.46,44.02 1.38,44.95 3.17,44.95 4.07,44.04
N12407237 on TOP: 18.4,43.23 18.4,41.8 17.76,41.16 16.54,41.16 15.12,42.57 11.38,42.57 9.96,41.16 8.13,41.16 7.37,41.91 7.37,44.02 8.31,44.96 16.67,44.96
N12407237 on BOTTOM: 18.4,43.21 18.4,41.79 17.75,41.14 16.54,41.14 15.1,42.58 11.4,42.58 9.97,41.15 8.13,41.15 7.36,41.91 7.36,44.06 8.26,44.96 16.66,44.96
N12433777 on BOTTOM: 58.98,2.87 59.66,2.87 61.1,4.31 61.93,4.31 62.55,3.69 62.55,2.84 61.17,1.46 58.99,1.46 58.98,1.47
N12606053 on BOTTOM: 57.35,9.02 58.62,9.02 58.86,8.78 58.86,5.94 57.89,5.94 57.89,7.01 57.38,7.52 57.35,7.52 57.25,7.62 57.25,8.92
N13222962 on BOTTOM (solid shape): 13.56,24.56 10.53,24.56 8.98,26.11 8.98,27.66 10.3,28.98 13.56,28.98
N13223037 on BOTTOM (solid shape): 20.93,27.51 20.93,25.96 19.56,24.59 16.59,24.59 16.59,29.01 19.44,29.01
N13228168 on BOTTOM: 65.41,10.59 67.08,10.59 67.16,10.52 67.16,5.84 66.8,5.49 65.23,5.49 64.97,5.74 64.97,9.47 65.41,9.91
N13228288 on BOTTOM: 41.4,35.03 42.79,35.03 42.93,34.89 42.93,30.96 42.8,30.84 41.39,30.84 41.25,30.98 41.25,34.88
N13228295 on BOTTOM: 41.36,25.02 41.24,25.14 41.24,29.09 41.36,29.21 42.8,29.21 42.92,29.09 42.92,25.15 42.79,25.02
N13238248 on BOTTOM (solid shape): 76.12,43.21 75.29,42.93 76.12,42.65 75.29,42.37 76.12,42.09 75.29,41.81 74.3,41.81 73.58,42.52 73.58,43.48 75.29,43.48
N13238248 on BOTTOM (solid shape): 71.45,43.23 71.45,41.95 71.25,41.76 69.19,41.76 69.19,41.77 68.38,42.04 69.22,42.32 68.38,42.6 69.22,42.88 68.38,43.15 69.22,43.43 71.25,43.43

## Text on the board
Ref Des/Silkscreen Bottom: TM | InnoSwitch  3-EP
Ref Des/Silkscreen Top: S/N: | DER-1025 | REV D | 2613
User.6: 11.  TRACE SPACE +/- 0.003" | 14. VIAS ARE TENTED | 13. 2 LAYERS BOARD: TOP,BOTTOM. | PLEASE DELETE THESE PINS
User.10: FIGURE | FINISHED_SIZE | 18.0 | 30.0 | 40.0 | 42.0 | 46.0 | 50.0 | 52.0 | 67.0 | 70.0 | DRILL CHART: TOP to BOTTOM | ALL UNITS ARE IN MILS | TOLERANCE_DRILL | +3.0/-3.0 | PLATED | QTY | 159 | 10 | 15 | 1 | 4 | 12 | 6 | 215 | TOTAL HOLES:
